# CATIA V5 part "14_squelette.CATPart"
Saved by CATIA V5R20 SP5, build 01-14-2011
Part number: 14_squelette
Publications: "Droite.1", "Point.2", "Plan yz"
Bounding box of the stored display mesh (mm): x 0 to 0, y -76 to 64, z 0 to 9.525
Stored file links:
  C:\Documents and Settings\anizard\Bureau\13\14_squelette.CATPart
  C:\Documents and Settings\anizard\Bureau\13\anizard.CATProduct
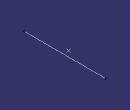
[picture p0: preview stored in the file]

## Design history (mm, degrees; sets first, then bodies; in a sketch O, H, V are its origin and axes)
Set1
  Point1: linked copy from another document
  Plane1: linked copy from another document
Body1 (main body)
  Line1: type PtDir, RefPoint Point1, Direction Plane1, Start -76, End 64
  Point2: (0, 0, 9.525), relative to Point1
